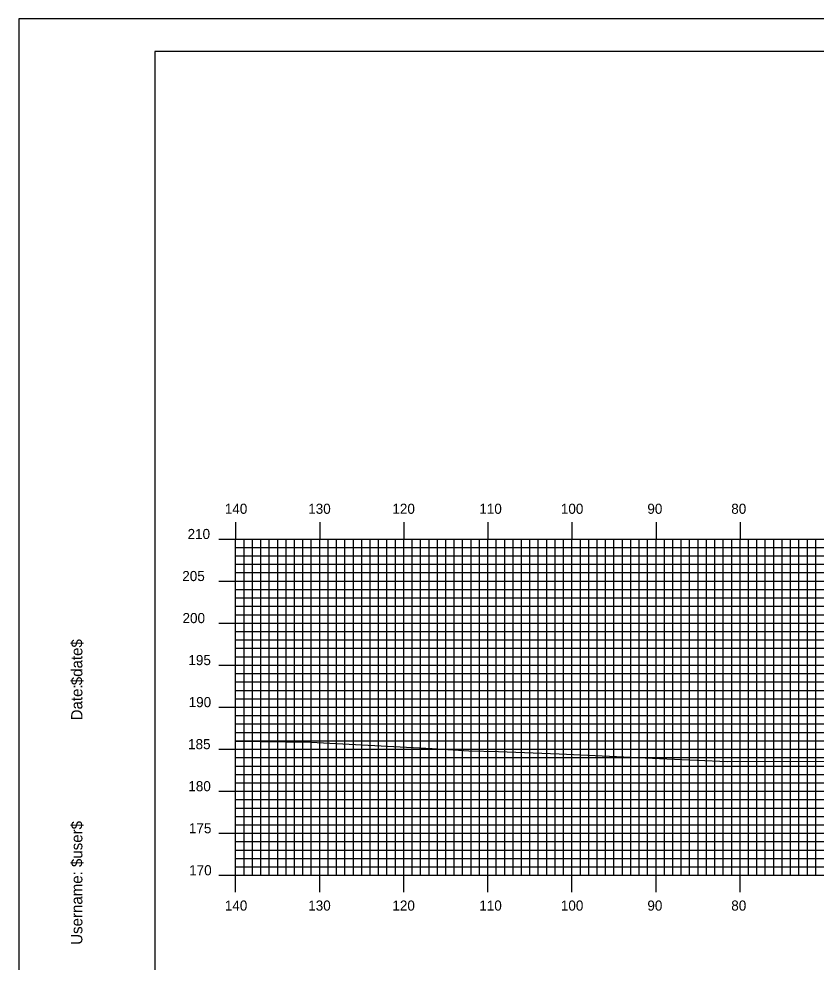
# Model space of a CAD drawing. Extents: x 1808619 to 1808962, y 442591 to 442811.
# Drawn here: x 1808619 to 1808713.9, y 442698.3 to 442810.5 of the extents above; entities that cross this region are included whole.
import ezdxf

# ---------------------------------------------------------------- set-up
doc = ezdxf.new("R2010")
doc.units = 0
for name, color, linetype in [('BORDER', 7, 'Continuous'), ('H_V ANNOTATION', 7, 'Continuous'), ('MAJOR', 7, 'Continuous'), ('MINOR', 7, 'Continuous'), ('PLOT BOUNDARY', 7, 'Continuous'), ('S_Roadway_Centerline', 7, 'Continuous')]:
    doc.layers.add(name, color=color, linetype=linetype)

msp = doc.modelspace()

# ---------------------------------------------------------------- linework, layer by layer
at = {"layer": 'BORDER'}
msp.add_lwpolyline([(1808635.21, 442596.67), (1808955.21, 442596.67), (1808955.21, 442806.67), (1808635.21, 442806.67)], close=True, dxfattribs=at)
at = {"layer": 'MAJOR'}
for p, q in [((1808644.81, 442750.67), (1808644.81, 442748.67)), ((1808654.81, 442750.67), (1808654.81, 442748.67)), ((1808664.81, 442750.67), (1808664.81, 442748.67)), ((1808674.81, 442750.67), (1808674.81, 442748.67)), ((1808684.81, 442750.67), (1808684.81, 442748.67)), ((1808694.81, 442750.67), (1808694.81, 442748.67)), ((1808704.81, 442750.67), (1808704.81, 442748.67)), ((1808642.81, 442748.67), (1808644.81, 442748.67)), ((1808644.81, 442748.67), (1808924.81, 442748.67)), ((1808644.81, 442708.67), (1808644.81, 442748.67)), ((1808644.81, 442708.67), (1808644.81, 442748.67)), ((1808644.81, 442748.67), (1808924.81, 442748.67)), ((1808654.81, 442708.67), (1808654.81, 442748.67)), ((1808664.81, 442708.67), (1808664.81, 442748.67)), ((1808674.81, 442708.67), (1808674.81, 442748.67)), ((1808684.81, 442708.67), (1808684.81, 442748.67)), ((1808694.81, 442708.67), (1808694.81, 442748.67)), ((1808704.81, 442708.67), (1808704.81, 442748.67)), ((1808642.81, 442743.67), (1808644.81, 442743.67)), ((1808644.81, 442743.67), (1808924.81, 442743.67)), ((1808642.81, 442738.67), (1808644.81, 442738.67)), ((1808644.81, 442738.67), (1808924.81, 442738.67)), ((1808642.81, 442733.67), (1808644.81, 442733.67)), ((1808644.81, 442733.67), (1808924.81, 442733.67)), ((1808642.81, 442728.67), (1808644.81, 442728.67)), ((1808644.81, 442728.67), (1808924.81, 442728.67)), ((1808642.81, 442723.67), (1808644.81, 442723.67)), ((1808644.81, 442723.67), (1808924.81, 442723.67)), ((1808642.81, 442718.67), (1808644.81, 442718.67)), ((1808644.81, 442718.67), (1808924.81, 442718.67)), ((1808642.81, 442713.67), (1808644.81, 442713.67)), ((1808644.81, 442713.67), (1808924.81, 442713.67)), ((1808642.81, 442708.67), (1808644.81, 442708.67)), ((1808644.81, 442708.67), (1808924.81, 442708.67)), ((1808644.81, 442708.67), (1808924.81, 442708.67)), ((1808644.81, 442706.66), (1808644.81, 442708.67)), ((1808654.81, 442706.66), (1808654.81, 442708.67)), ((1808664.81, 442706.66), (1808664.81, 442708.67)), ((1808674.81, 442706.66), (1808674.81, 442708.67)), ((1808684.81, 442706.66), (1808684.81, 442708.67)), ((1808694.81, 442706.66), (1808694.81, 442708.67)), ((1808704.81, 442706.66), (1808704.81, 442708.67))]:
    msp.add_line(p, q, dxfattribs=at)
at = {"layer": 'MINOR'}
for p, q in [((1808645.81, 442708.67), (1808645.81, 442748.67)), ((1808646.81, 442708.67), (1808646.81, 442748.67)), ((1808647.81, 442708.67), (1808647.81, 442748.67)), ((1808648.81, 442708.67), (1808648.81, 442748.67)), ((1808649.81, 442708.67), (1808649.81, 442748.67)), ((1808650.81, 442708.67), (1808650.81, 442748.67)), ((1808651.81, 442708.67), (1808651.81, 442748.67)), ((1808652.81, 442708.67), (1808652.81, 442748.67)), ((1808653.81, 442708.67), (1808653.81, 442748.67)), ((1808655.81, 442708.67), (1808655.81, 442748.67)), ((1808656.81, 442708.67), (1808656.81, 442748.67)), ((1808657.81, 442708.67), (1808657.81, 442748.67)), ((1808658.81, 442708.67), (1808658.81, 442748.67)), ((1808659.81, 442708.67), (1808659.81, 442748.67)), ((1808660.81, 442708.67), (1808660.81, 442748.67)), ((1808661.81, 442708.67), (1808661.81, 442748.67)), ((1808662.81, 442708.67), (1808662.81, 442748.67)), ((1808663.81, 442708.67), (1808663.81, 442748.67)), ((1808665.81, 442708.67), (1808665.81, 442748.67)), ((1808666.81, 442708.67), (1808666.81, 442748.67)), ((1808667.81, 442708.67), (1808667.81, 442748.67)), ((1808668.81, 442708.67), (1808668.81, 442748.67)), ((1808669.81, 442708.67), (1808669.81, 442748.67)), ((1808670.81, 442708.67), (1808670.81, 442748.67)), ((1808671.81, 442708.67), (1808671.81, 442748.67)), ((1808672.81, 442708.67), (1808672.81, 442748.67)), ((1808673.81, 442708.67), (1808673.81, 442748.67)), ((1808675.81, 442708.67), (1808675.81, 442748.67)), ((1808676.81, 442708.67), (1808676.81, 442748.67)), ((1808677.81, 442708.67), (1808677.81, 442748.67)), ((1808678.81, 442708.67), (1808678.81, 442748.67)), ((1808679.81, 442708.67), (1808679.81, 442748.67)), ((1808680.81, 442708.67), (1808680.81, 442748.67)), ((1808681.81, 442708.67), (1808681.81, 442748.67)), ((1808682.81, 442708.67), (1808682.81, 442748.67)), ((1808683.81, 442708.67), (1808683.81, 442748.67)), ((1808685.81, 442708.67), (1808685.81, 442748.67)), ((1808686.81, 442708.67), (1808686.81, 442748.67)), ((1808687.81, 442708.67), (1808687.81, 442748.67)), ((1808688.81, 442708.67), (1808688.81, 442748.67)), ((1808689.81, 442708.67), (1808689.81, 442748.67)), ((1808690.81, 442708.67), (1808690.81, 442748.67)), ((1808691.81, 442708.67), (1808691.81, 442748.67)), ((1808692.81, 442708.67), (1808692.81, 442748.67)), ((1808693.81, 442708.67), (1808693.81, 442748.67)), ((1808695.81, 442708.67), (1808695.81, 442748.67)), ((1808696.81, 442708.67), (1808696.81, 442748.67)), ((1808697.81, 442708.67), (1808697.81, 442748.67)), ((1808698.81, 442708.67), (1808698.81, 442748.67)), ((1808699.81, 442708.67), (1808699.81, 442748.67)), ((1808700.81, 442708.67), (1808700.81, 442748.67)), ((1808701.81, 442708.67), (1808701.81, 442748.67)), ((1808702.81, 442708.67), (1808702.81, 442748.67)), ((1808703.81, 442708.67), (1808703.81, 442748.67)), ((1808705.81, 442708.67), (1808705.81, 442748.67)), ((1808706.81, 442708.67), (1808706.81, 442748.67)), ((1808707.81, 442708.67), (1808707.81, 442748.67)), ((1808708.81, 442708.67), (1808708.81, 442748.67)), ((1808709.81, 442708.67), (1808709.81, 442748.67)), ((1808710.81, 442708.67), (1808710.81, 442748.67)), ((1808711.81, 442708.67), (1808711.81, 442748.67)), ((1808712.81, 442708.67), (1808712.81, 442748.67)), ((1808713.81, 442708.67), (1808713.81, 442748.67)), ((1808644.81, 442747.67), (1808924.81, 442747.67)), ((1808644.81, 442747.67), (1808646.82, 442747.67)), ((1808644.81, 442746.67), (1808924.81, 442746.67)), ((1808644.81, 442746.67), (1808646.82, 442746.67)), ((1808644.81, 442745.67), (1808924.81, 442745.67)), ((1808644.81, 442745.67), (1808646.82, 442745.67)), ((1808644.81, 442744.67), (1808924.81, 442744.67)), ((1808644.81, 442744.67), (1808646.82, 442744.67)), ((1808644.81, 442742.67), (1808924.81, 442742.67)), ((1808644.81, 442742.67), (1808646.82, 442742.67)), ((1808644.81, 442741.67), (1808924.81, 442741.67)), ((1808644.81, 442741.67), (1808646.82, 442741.67)), ((1808644.81, 442740.67), (1808924.81, 442740.67)), ((1808644.81, 442740.67), (1808646.82, 442740.67)), ((1808644.81, 442739.67), (1808924.81, 442739.67)), ((1808644.81, 442739.67), (1808646.82, 442739.67)), ((1808644.81, 442737.67), (1808924.81, 442737.67)), ((1808644.81, 442737.67), (1808646.82, 442737.67)), ((1808644.81, 442736.67), (1808924.81, 442736.67)), ((1808644.81, 442736.67), (1808646.82, 442736.67)), ((1808644.81, 442735.67), (1808924.81, 442735.67)), ((1808644.81, 442735.67), (1808646.82, 442735.67)), ((1808644.81, 442734.67), (1808924.81, 442734.67)), ((1808644.81, 442734.67), (1808646.82, 442734.67)), ((1808644.81, 442732.67), (1808924.81, 442732.67)), ((1808644.81, 442732.67), (1808646.82, 442732.67)), ((1808644.81, 442731.67), (1808924.81, 442731.67)), ((1808644.81, 442731.67), (1808646.82, 442731.67)), ((1808644.81, 442730.67), (1808924.81, 442730.67)), ((1808644.81, 442730.67), (1808646.82, 442730.67)), ((1808644.81, 442729.67), (1808924.81, 442729.67)), ((1808644.81, 442729.67), (1808646.82, 442729.67)), ((1808644.81, 442727.67), (1808924.81, 442727.67)), ((1808644.81, 442727.67), (1808646.82, 442727.67)), ((1808644.81, 442726.67), (1808924.81, 442726.67)), ((1808644.81, 442726.67), (1808646.82, 442726.67)), ((1808644.81, 442725.67), (1808924.81, 442725.67)), ((1808644.81, 442725.67), (1808646.82, 442725.67)), ((1808644.81, 442724.67), (1808924.81, 442724.67)), ((1808644.81, 442724.67), (1808646.82, 442724.67)), ((1808644.81, 442722.67), (1808924.81, 442722.67)), ((1808644.81, 442722.67), (1808646.82, 442722.67)), ((1808644.81, 442721.67), (1808924.81, 442721.67)), ((1808644.81, 442721.67), (1808646.82, 442721.67)), ((1808644.81, 442720.67), (1808924.81, 442720.67)), ((1808644.81, 442720.67), (1808646.82, 442720.67)), ((1808644.81, 442719.67), (1808924.81, 442719.67)), ((1808644.81, 442719.67), (1808646.82, 442719.67)), ((1808644.81, 442717.67), (1808924.81, 442717.67)), ((1808644.81, 442717.67), (1808646.82, 442717.67)), ((1808644.81, 442716.67), (1808924.81, 442716.67)), ((1808644.81, 442716.67), (1808646.82, 442716.67)), ((1808644.81, 442715.67), (1808924.81, 442715.67)), ((1808644.81, 442715.67), (1808646.82, 442715.67)), ((1808644.81, 442714.67), (1808924.81, 442714.67)), ((1808644.81, 442714.67), (1808646.82, 442714.67)), ((1808644.81, 442712.67), (1808924.81, 442712.67)), ((1808644.81, 442712.67), (1808646.82, 442712.67)), ((1808644.81, 442711.67), (1808924.81, 442711.67)), ((1808644.81, 442711.67), (1808646.82, 442711.67)), ((1808644.81, 442710.67), (1808924.81, 442710.67)), ((1808644.81, 442710.67), (1808646.82, 442710.67)), ((1808644.81, 442709.67), (1808924.81, 442709.67)), ((1808644.81, 442709.67), (1808646.82, 442709.67))]:
    msp.add_line(p, q, dxfattribs=at)
at = {"layer": 'PLOT BOUNDARY'}
msp.add_lwpolyline([(1808619.02, 442590.55), (1808959.02, 442590.55), (1808959.02, 442810.55), (1808619.02, 442810.55)], close=True, dxfattribs=at)
at = {"layer": 'S_Roadway_Centerline'}
msp.add_lwpolyline([(1808644.81, 442724.62), (1808653.76, 442724.52), (1808668.17, 442723.74), (1808672.56, 442723.48), (1808676.08, 442723.38), (1808683.29, 442723.1), (1808696.1, 442722.53), (1808703.3, 442722.21), (1808718.65, 442722.23)], dxfattribs=at)

# ---------------------------------------------------------------- texts
at = {"layer": 'BORDER'}
for s, p in [('$date$', (1808626.58, 442731.28)), ('Date:', (1808626.58, 442727.1)), ('$user$', (1808626.58, 442709.65)), ('Username:', (1808626.58, 442700.4))]:
    msp.add_text(s, height=1.339, rotation=90, dxfattribs=at).set_placement(p)
at = {"layer": 'H_V ANNOTATION'}
for s, p in [('140', (1808643.52, 442751.67)), ('130', (1808653.44, 442751.67)), ('120', (1808663.45, 442751.67)), ('110', (1808673.79, 442751.67)), ('100', (1808683.49, 442751.67)), ('90', (1808693.78, 442751.67)), ('80', (1808703.76, 442751.67)), ('210', (1808639.09, 442748.67)), ('205', (1808638.46, 442743.67)), ('200', (1808638.49, 442738.67)), ('195', (1808639.19, 442733.67)), ('190', (1808639.22, 442728.67)), ('185', (1808639.15, 442723.67)), ('180', (1808639.18, 442718.67)), ('175', (1808639.25, 442713.67)), ('170', (1808639.28, 442708.67)), ('140', (1808643.52, 442704.47)), ('130', (1808653.44, 442704.47)), ('120', (1808663.45, 442704.47)), ('110', (1808673.79, 442704.47)), ('100', (1808683.49, 442704.47)), ('90', (1808693.78, 442704.47)), ('80', (1808703.76, 442704.47))]:
    msp.add_text(s, height=1.2, dxfattribs=at).set_placement(p)
at = {"layer": 'MAJOR'}
msp.add_text('-', height=0.012, dxfattribs=at).set_placement((1808644.8, 442708.67))

doc.saveas('drawing.dxf')
